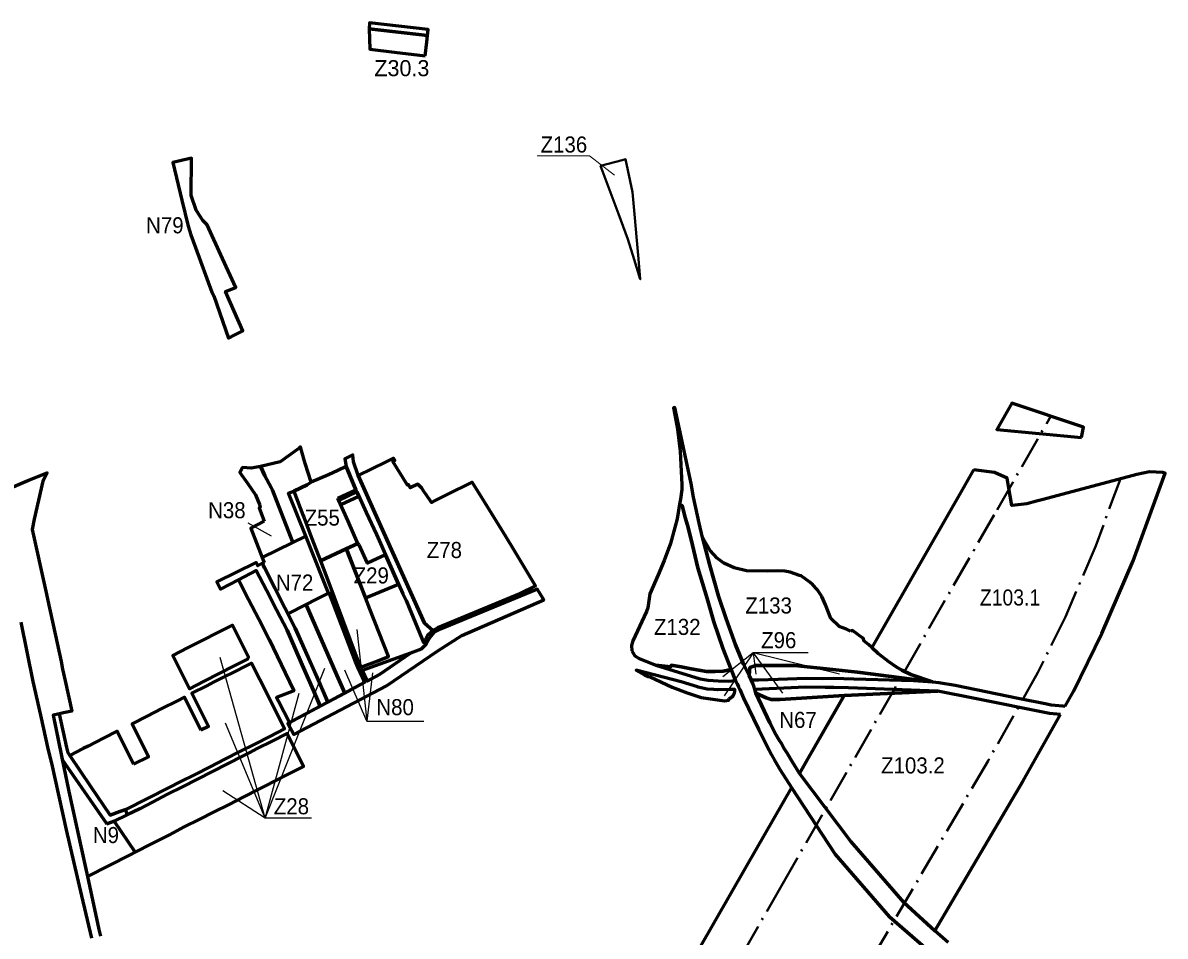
# Model space of a CAD drawing. Extents: x -650277 to -643425, y -1073980 to -1066720.
# Drawn here: x -648765 to -647061, y -1068122 to -1066758 of the extents above; entities that cross this region are included whole.
import ezdxf

# ---------------------------------------------------------------- set-up
doc = ezdxf.new("R2010")
doc.units = 0
doc.header["$LTSCALE"] = 9.6
doc.linetypes.add('DOT_DASHED', pattern=[7.7, 5, -1.2, 0.3, -1.2])
for name, color, linetype, lineweight in [('1', 7, 'Continuous', 60), ('15', 7, 'Continuous', 60), ('2', 7, 'Continuous', 40), ('3', 7, 'Continuous', 60), ('42', 7, 'Continuous', 60), ('45', 7, 'Continuous', 60), ('48', 7, 'Continuous', 60), ('59', 7, 'Continuous', 25), ('60', 7, 'Continuous', 60), ('61', 7, 'Continuous', 60), ('62', 7, 'DOT_DASHED', 40), ('63', 7, 'Continuous', 25), ('7', 7, 'Continuous', 60), ('9', 7, 'Continuous', 60)]:
    doc.layers.add(name, color=color, linetype=linetype, lineweight=lineweight)

msp = doc.modelspace()

# ---------------------------------------------------------------- linework, layer by layer
at = {"layer": '1'}
msp.add_line((-648609.91, -1067940.58), (-648611.61, -1067932.63), dxfattribs=at)
for points in [[(-647708.71, -1067723.99), (-647721.05, -1067691.73), (-647734.63, -1067652.57), (-647744.61, -1067617.96), (-647758.25, -1067571.79), (-647768.5, -1067529.75), (-647773.96, -1067508.48), (-647777.55, -1067496.95), (-647781.85, -1067479.19), (-647785.64, -1067477.02), (-647789.39, -1067498.84), (-647792.54, -1067511.85), (-647799.39, -1067535.48)], [(-647704.458, -1067572.034), (-647719.661, -1067564.884), (-647729.802, -1067557.462), (-647740.124, -1067546.265), (-647751.41, -1067526.58), (-647740.49, -1067568.67), (-647727.37, -1067614.33), (-647715.92, -1067648.12), (-647702.04, -1067686.86), (-647690.09, -1067716.05), (-647681.91, -1067732.74), (-647680.804, -1067720.745), (-647672, -1067718), (-647643, -1067718), (-647614, -1067718), (-647557, -1067724), (-647520.145, -1067727.879), (-647408.2, -1067742.37)], [(-648263.7, -1067537.93), (-648265.757, -1067535.555), (-648282.863, -1067543.596), (-648281.774, -1067546.369), (-648254.04, -1067616.96)], [(-648224.16, -1067552.55), (-648251.33, -1067565.28), (-648263.7, -1067537.93)], [(-647799.39, -1067535.48), (-647808.71, -1067561.03), (-647817.59, -1067582.4)], [(-648254.04, -1067616.96), (-648204.88, -1067596.54), (-648224.16, -1067552.55)], [(-647591.227, -1067593.613), (-647604.415, -1067584.047), (-647606.559, -1067583.309), (-647620.586, -1067578.478), (-647628.441, -1067576.759), (-647640.087, -1067576.306), (-647654.743, -1067576.996), (-647685.968, -1067576.68), (-647704.458, -1067572.034)], [(-647817.59, -1067582.4), (-647829.97, -1067610.62), (-647832.8, -1067631.53), (-647835.06, -1067637.01), (-647855.24, -1067681.26), (-647857.51, -1067687.74), (-647856.9, -1067695.97)], [(-647573.605, -1067614.951), (-647580.539, -1067604.432), (-647586.864, -1067597.411), (-647591.227, -1067593.613)], [(-647530.82, -1067666.65), (-647536.83, -1067663.64), (-647547.663, -1067659.519), (-647560.187, -1067647.458), (-647567.744, -1067627.24), (-647573.605, -1067614.951)], [(-647499.095, -1067691.163), (-647503.97, -1067686.73), (-647510.6, -1067680.86), (-647511.24, -1067677.53), (-647517.74, -1067672.85), (-647520.13, -1067671.13), (-647527.76, -1067665.65), (-647530.82, -1067666.65)], [(-647856.9, -1067695.97), (-647852.3, -1067703.36), (-647845.74, -1067707.59), (-647821.02, -1067717.33)], [(-647474.13, -1067711.81), (-647489.3, -1067700.07), (-647499.095, -1067691.163)], [(-648399.64, -1067763.26), (-648424.14, -1067714.34), (-648435.34, -1067720.01), (-648446.58, -1067725.71), (-648468.97, -1067736.91), (-648480.06, -1067742.47), (-648491.14, -1067748.02), (-648513.23, -1067759.38), (-648488.49, -1067808.76), (-648499.7, -1067814.37)], [(-647453.87, -1067724.97), (-647462.45, -1067719.84), (-647474.13, -1067711.81)], [(-647821.02, -1067717.33), (-647798.5, -1067719.67), (-647798.17, -1067717.58), (-647783.13, -1067719.68), (-647768.53, -1067722.82), (-647745.41, -1067726.6), (-647732.71, -1067727.02), (-647720.45, -1067726.49), (-647708.71, -1067723.99)], [(-647408.2, -1067742.37), (-647440.81, -1067731.38), (-647453.87, -1067724.97)], [(-648611.61, -1067932.63), (-648547.09, -1067899.87), (-648530.81, -1067891.61), (-648508.22, -1067880.38), (-648486.09, -1067868.98), (-648463.91, -1067857.74), (-648441.47, -1067846.37), (-648419.44, -1067835.3), (-648397.04, -1067823.85), (-648374.84, -1067812.43), (-648399.64, -1067763.26)], [(-648499.7, -1067814.37), (-648524.44, -1067765.11), (-648535.61, -1067770.85), (-648557.84, -1067782.26), (-648580.14, -1067793.61), (-648602.3, -1067804.83), (-648577.78, -1067854.07), (-648600.14, -1067865.29)], [(-648600.14, -1067865.29), (-648624.76, -1067816.11), (-648645.11, -1067826.48), (-648668.085, -1067838.186), (-648675.26, -1067841.84), (-648695.27, -1067852.04), (-648664.41, -1067897.91)], [(-648572.5, -1067983.59), (-648546.76, -1067970.44), (-648524.72, -1067958.93), (-648502.59, -1067948), (-648480.12, -1067936.55), (-648457.87, -1067925.4), (-648435.55, -1067913.84), (-648413.41, -1067902.53), (-648402.29, -1067897.02), (-648391.08, -1067891.24), (-648368.78, -1067879.75), (-648346.57, -1067868.56), (-648371.27, -1067819.47), (-648393.35, -1067830.81), (-648415.69, -1067841.98), (-648426.65, -1067847.64), (-648437.89, -1067853.4), (-648460.33, -1067864.88), (-648482.5, -1067876.22), (-648504.92, -1067887.52), (-648527.33, -1067898.74), (-648549.44, -1067910.07), (-648571.88, -1067921.71), (-648591.04, -1067931.62), (-648609.91, -1067940.58)], [(-648664.41, -1067897.91), (-648635.249, -1067941.252), (-648620.658, -1067935.93), (-648611.61, -1067932.63)], [(-648609.91, -1067940.58), (-648629.22, -1067950.214), (-648597.93, -1067996.72), (-648572.5, -1067983.59)]]:
    msp.add_lwpolyline(points, dxfattribs=at)
for points in [[(-648397.98, -1067678.79), (-648373.99, -1067728.95), (-648361.08, -1067755.88), (-648387.04, -1067765.67), (-648384.25, -1067771.07), (-648367.811, -1067802.994), (-648321.623, -1067778.399), (-648326, -1067769), (-648337.32, -1067742.59), (-648348.55, -1067716.71), (-648359.6, -1067691.58), (-648371.34, -1067665.08), (-648386.91, -1067634.83), (-648402.02, -1067605.49), (-648417.12, -1067576.17), (-648443.83, -1067589.92), (-648428.7, -1067619.24), (-648413.57, -1067648.57)], [(-648342.697, -1067626.806), (-648369.949, -1067640.851), (-648359.213, -1067661.956), (-648310.511, -1067772.476), (-648285.254, -1067759.008), (-648296.891, -1067732.172), (-648342.023, -1067628.096)], [(-648519.63, -1067691.58), (-648541.86, -1067702.86), (-648516.73, -1067752.57), (-648494.84, -1067741.06), (-648472.5, -1067729.76), (-648450.23, -1067718.32), (-648430.17, -1067708.33), (-648428.67, -1067705.52), (-648452.72, -1067657.62)]]:
    msp.add_lwpolyline(points, close=True, dxfattribs=at)
at = {"layer": '1', "lineweight": 25}
msp.add_lwpolyline([(-648335, -1067946), (-648404, -1067946), (-648353, -1067759)], dxfattribs=at)
at = {"layer": '15'}
msp.add_line((-648264.34, -1067464.83), (-648267.21, -1067458.61), dxfattribs=at)
msp.add_line((-648264.34, -1067464.83), (-648267.21, -1067458.61), dxfattribs=at)
msp.add_line((-648264.34, -1067464.83), (-648267.21, -1067458.61), dxfattribs=at)
for points in [[(-648161.58, -1066777.41), (-648160.51, -1066768.4), (-648248.43, -1066758.34), (-648248.77, -1066767.43)], [(-648362.585, -1067534.204), (-648343.41, -1067524.81), (-648369.01, -1067460.52), (-648361, -1067457.36), (-648341.15, -1067448.14), (-648335.38, -1067444.07), (-648344.41, -1067416.04), (-648349.67, -1067396.88), (-648351.06, -1067391.62), (-648352.16, -1067392.42), (-648353.35, -1067393.29), (-648381.48, -1067413.68), (-648410.92, -1067420.63), (-648409.61, -1067423.44), (-648404.29, -1067434.9), (-648394.92, -1067452.23), (-648393.17, -1067455.88)], [(-648237.81, -1067522.42), (-648204.88, -1067596.54), (-648198.39, -1067610.97), (-648193.8, -1067621), (-648189.03, -1067631.71), (-648167.48, -1067683.45), (-648164.79, -1067678.96), (-648163.11, -1067676.17), (-648160.68, -1067671.55), (-648153.98, -1067665.43), (-648166.173, -1067654.853), (-648240.51, -1067489.9), (-648265.197, -1067434.03), (-648265.197, -1067434.03), (-648272.022, -1067413.59), (-648273.008, -1067403.338), (-648279.24, -1067406.38), (-648285.08, -1067409.24), (-648283.21, -1067420.88), (-648268.67, -1067455.43), (-648267.21, -1067458.61), (-648264.34, -1067464.83), (-648253.1, -1067489.23)], [(-648359.6, -1067691.58), (-648348.55, -1067716.71), (-648337.32, -1067742.59), (-648326, -1067769), (-648321.623, -1067778.399), (-648310.511, -1067772.476), (-648323.178, -1067741.953), (-648359.213, -1067661.956), (-648405.054, -1067571.837), (-648408.002, -1067565.219), (-648414.73, -1067568.8), (-648417.19, -1067564.02), (-648475.78, -1067593.11), (-648473.34, -1067598.06), (-648470.57, -1067603.69), (-648470.47, -1067603.64), (-648443.83, -1067589.92), (-648417.12, -1067576.17), (-648402.02, -1067605.49), (-648386.91, -1067634.83), (-648371.34, -1067665.08)], [(-647988.235, -1067619.912), (-647995.04, -1067608.56), (-647997.68, -1067604.11), (-648144.83, -1067664.48), (-648151.6, -1067668.12), (-648157.2, -1067674.32), (-648161, -1067680.96), (-648162.69, -1067684), (-648164.09, -1067686.51), (-648171.21, -1067693.37), (-648187.139, -1067699.179), (-648233.264, -1067731.288), (-648251.711, -1067741.124), (-648258.96, -1067725.37), (-648262.632, -1067726.711), (-648255.016, -1067742.886), (-648319.983, -1067777.526), (-648370.113, -1067804.22), (-648360.993, -1067821.027), (-648222.872, -1067748.412), (-648146.127, -1067695.8), (-648110.36, -1067673.133), (-647988.052, -1067619.624)]]:
    msp.add_lwpolyline(points, close=True, dxfattribs=at)
for points in [[(-648793.71, -1067456.88), (-648757.97, -1067441.51), (-648728.95, -1067430.33), (-648735.59, -1067442.88), (-648748.53, -1067499.3), (-648751.29, -1067514.57), (-648731.06, -1067607.06), (-648725.8, -1067632.36), (-648720.1, -1067657.12), (-648708.26, -1067712.07), (-648706.08, -1067723.56), (-648702.33, -1067740.84), (-648692.53, -1067785.79), (-648704.614, -1067788.491), (-648710.961, -1067789.906), (-648720.34, -1067792), (-648696.93, -1067905.76), (-648672.31, -1068017.25), (-648668.92, -1068032.96), (-648651.89, -1068111.95), (-648649.74, -1068121.95)], [(-648267.21, -1067458.61), (-648294.04, -1067471.35), (-648291.172, -1067477.571), (-648264.34, -1067464.83)], [(-648267.21, -1067458.61), (-648294.04, -1067471.35), (-648291.172, -1067477.571), (-648264.34, -1067464.83)], [(-648267.21, -1067458.61), (-648294.04, -1067471.35), (-648291.172, -1067477.571), (-648264.34, -1067464.83)], [(-648662.71, -1068124.76), (-648677.61, -1068061.74), (-648700.16, -1067963.42), (-648722.09, -1067863.84), (-648727.05, -1067844.33), (-648738.7, -1067792.04), (-648749.97, -1067741.49), (-648767.84, -1067652.98)], [(-648710.961, -1067789.906), (-648720.34, -1067792), (-648706.687, -1067858.345), (-648640, -1067954)], [(-648695.27, -1067852.04), (-648697.7, -1067848.43), (-648699.621, -1067840.06), (-648699.593, -1067840.046), (-648710.96, -1067789.91)], [(-648611.61, -1067932.63), (-648620.658, -1067935.93), (-648635.249, -1067941.252), (-648664.41, -1067897.91), (-648695.27, -1067852.04)], [(-648640, -1067954), (-648629.22, -1067950.214), (-648609.91, -1067940.58), (-648611.61, -1067932.63)]]:
    msp.add_lwpolyline(points, dxfattribs=at)
at = {"layer": '2'}
msp.add_lwpolyline([(-647876.57, -1067043.5), (-647863.04, -1067081.36), (-647853.65, -1067111.91), (-647844.3, -1067141.25), (-647847.09, -1067110.58), (-647850.07, -1067077.71), (-647852.63, -1067049.52), (-647856.11, -1067011.21), (-647866.14, -1066961.98), (-647871.52, -1066963.43), (-647903.5, -1066972.05), (-647903.5, -1066972.05)], close=True, dxfattribs=at)
at = {"layer": '3'}
msp.add_lwpolyline([(-648165.33, -1066807.74), (-648162.8, -1066786.8), (-648161.58, -1066777.41), (-648248.77, -1066767.43), (-648247.78, -1066797.53), (-648211.58, -1066802.18)], close=True, dxfattribs=at)
at = {"layer": '42'}
msp.add_lwpolyline([(-647606.818, -1067879.061), (-647540.208, -1067762.876), (-647635.758, -1067768.38), (-647649.22, -1067768.38), (-647656.469, -1067766.309), (-647672.05, -1067758.98), (-647650.8, -1067803.28), (-647642.29, -1067820.76), (-647637.21, -1067829.29), (-647633.69, -1067834.31), (-647630.3, -1067841.02), (-647625.37, -1067848.86), (-647617.25, -1067861.95)], close=True, dxfattribs=at)
at = {"layer": '45'}
msp.add_lwpolyline([(-648405.41, -1067563.84), (-648408.002, -1067565.219), (-648369.949, -1067640.851), (-648342.697, -1067626.806), (-648328.54, -1067619.51), (-648309.522, -1067609.713), (-648317.43, -1067590), (-648343.41, -1067524.81), (-648408.26, -1067556.58)], close=True, dxfattribs=at)
at = {"layer": '48'}
for points in [[(-648528.01, -1067023.13), (-648518.72, -1067061.99), (-648514.86, -1067074.83), (-648507.88, -1067093.9), (-648483.31, -1067160.63), (-648480.57, -1067166.13), (-648458.73, -1067229.1), (-648449.03, -1067224.14), (-648437.02, -1067217.99), (-648462.97, -1067159.24), (-648447.66, -1067153.25), (-648467.56, -1067110.02), (-648490.23, -1067060.06), (-648496.87, -1067053.5), (-648506.78, -1067037.81), (-648514.38, -1067016.2), (-648513.842, -1066960.243), (-648541.52, -1066966.657)], [(-648405.27, -1067502.27), (-648425.5, -1067512.73), (-648408.26, -1067556.58), (-648362.585, -1067534.205), (-648393.17, -1067455.88), (-648394.92, -1067452.23), (-648404.29, -1067434.9), (-648410.92, -1067420.63), (-648425, -1067423.05), (-648437.75, -1067421.99), (-648441.48, -1067429.63), (-648430.4, -1067445.51), (-648418.3, -1067462.86), (-648412.46, -1067477.42), (-648411.25, -1067481.73), (-648412.89, -1067482.55)], [(-648342.023, -1067628.096), (-648296.891, -1067732.172), (-648285.254, -1067759.008), (-648255.016, -1067742.886), (-648265.614, -1067720.378), (-648269.27, -1067712.6), (-648308.43, -1067609.15), (-648328.54, -1067619.51), (-648342.697, -1067626.806)], [(-648258.96, -1067725.37), (-648251.711, -1067741.124), (-648233.264, -1067731.288), (-648187.139, -1067699.179)]]:
    msp.add_lwpolyline(points, close=True, dxfattribs=at)
for points in [[(-648295.409, -1067468.129), (-648268.67, -1067455.43), (-648283.21, -1067420.88), (-648295.66, -1067426.76), (-648309.57, -1067433.34), (-648335.38, -1067444.07), (-648341.15, -1067448.14), (-648361, -1067457.36), (-648347.51, -1067492.87), (-648346.27, -1067496.14)], [(-648346.27, -1067496.14), (-648334.09, -1067528.2), (-648321.36, -1067561.69), (-648282.863, -1067543.596), (-648265.757, -1067535.555), (-648279.86, -1067502.11), (-648294.04, -1067471.35), (-648295.409, -1067468.129)], [(-648265.08, -1067712.06), (-648261.25, -1067720.39), (-648235.78, -1067710.79), (-648219.86, -1067704.42), (-648247.53, -1067633.53), (-648254.04, -1067616.96), (-648282.863, -1067543.596), (-648321.36, -1067561.69)], [(-648321.361, -1067561.69), (-648311.95, -1067586.45), (-648265.08, -1067712.06)]]:
    msp.add_lwpolyline(points, dxfattribs=at)
at = {"layer": '59', "lineweight": 13}
msp.add_lwpolyline([(-647998, -1066957), (-647920, -1066957), (-647883, -1066986)], dxfattribs=at)
at = {"layer": '60'}
for points in [[(-647606.818, -1067879.061), (-647617.25, -1067861.95), (-647625.37, -1067848.86), (-647630.3, -1067841.02), (-647633.69, -1067834.31), (-647637.21, -1067829.29), (-647642.29, -1067820.76), (-647650.8, -1067803.28), (-647672.05, -1067758.98), (-647673.47, -1067753.48), (-647673.47, -1067753.48), (-647674.67, -1067748.73), (-647676.47, -1067744.5), (-647678.66, -1067739.38), (-647681.91, -1067732.74), (-647690.09, -1067716.05), (-647702.04, -1067686.86), (-647715.92, -1067648.12), (-647727.37, -1067614.33), (-647740.49, -1067568.67), (-647751.41, -1067526.58), (-647756.55, -1067505.32), (-647759.16, -1067494.01), (-647764.89, -1067466.64), (-647768.5, -1067446.04), (-647778.78, -1067397.1), (-647792.52, -1067332.74), (-647794.54, -1067333.14), (-647788.77, -1067365.03), (-647784.55, -1067398.01), (-647782.39, -1067448.34), (-647782.5, -1067455.11), (-647784.36, -1067469.6), (-647785.64, -1067477.02), (-647781.85, -1067479.19), (-647777.55, -1067496.95), (-647773.96, -1067508.48), (-647768.5, -1067529.75), (-647758.25, -1067571.79), (-647744.61, -1067617.96), (-647734.63, -1067652.57), (-647721.05, -1067691.73), (-647708.71, -1067723.99), (-647702.21, -1067740.43), (-647699.89, -1067745.24), (-647697.85, -1067749.46), (-647695.71, -1067753.9), (-647690.19, -1067766.37), (-647668.13, -1067812.76), (-647651.94, -1067844.36), (-647648.33, -1067851.17), (-647643.83, -1067859.13), (-647635.77, -1067873.43), (-647618.773, -1067899.914)], [(-647783.54, -1067742.11), (-647850.45, -1067724.77), (-647838.18, -1067731.62), (-647832.56, -1067734.22), (-647829.49, -1067734.58), (-647796.87, -1067750.25), (-647774.54, -1067758.68), (-647753.53, -1067765.58), (-647718.54, -1067770.6), (-647712.01, -1067769.63), (-647712.26, -1067767.28)], [(-647712.26, -1067767.28), (-647711.773, -1067767.135), (-647711.286, -1067766.968), (-647710.799, -1067766.777), (-647710.315, -1067766.562), (-647709.834, -1067766.324), (-647709.359, -1067766.062), (-647708.892, -1067765.776), (-647708.433, -1067765.466), (-647707.985, -1067765.133), (-647707.55, -1067764.777), (-647707.128, -1067764.398), (-647706.723, -1067763.999), (-647706.335, -1067763.579), (-647705.966, -1067763.14), (-647705.617, -1067762.683), (-647705.29, -1067762.21), (-647704.985, -1067761.721), (-647704.704, -1067761.22), (-647704.447, -1067760.707), (-647704.216, -1067760.184), (-647704.01, -1067759.653), (-647703.83, -1067759.117), (-647703.675, -1067758.576), (-647703.547, -1067758.033), (-647703.445, -1067757.489), (-647703.368, -1067756.946), (-647703.315, -1067756.406), (-647703.287, -1067755.87), (-647703.282, -1067755.341), (-647703.3, -1067754.818), (-647703.34, -1067754.304), (-647703.4, -1067753.8), (-647711.09, -1067753.71), (-647728.98, -1067754.07), (-647734.69, -1067753.66), (-647744.74, -1067752.93), (-647757.74, -1067749.96), (-647759.13, -1067749.54), (-647783.54, -1067742.11)], [(-647405.026, -1068113.904), (-647451.024, -1068071.886), (-647530.038, -1067980.839), (-647606.818, -1067879.061)], [(-647618.773, -1067899.914), (-647553.628, -1067999.427), (-647472.338, -1068093.096), (-647419.713, -1068138.871)], [(-647385.13, -1068131.51), (-647405.026, -1068113.904)]]:
    msp.add_lwpolyline(points, dxfattribs=at)
for points in [[(-647754.88, -1067737.59), (-647743.12, -1067739.93), (-647728.29, -1067740.64), (-647713.15, -1067741), (-647702.21, -1067740.43), (-647708.71, -1067723.99), (-647720.45, -1067726.49), (-647732.71, -1067727.02), (-647745.41, -1067726.6), (-647768.53, -1067722.82), (-647783.13, -1067719.68), (-647798.17, -1067717.58), (-647798.5, -1067719.67), (-647821.02, -1067717.33)], [(-647596.91, -1067736.61), (-647572.33, -1067737.03), (-647555.58, -1067736.71), (-647525.685, -1067737.542), (-647436.72, -1067740.02), (-647408.2, -1067742.37), (-647520.145, -1067727.879), (-647557, -1067724), (-647614, -1067718), (-647643, -1067718), (-647672, -1067718), (-647680.804, -1067720.745), (-647681.91, -1067732.74), (-647678.66, -1067739.38), (-647678.66, -1067739.38), (-647667.76, -1067739.01), (-647638.75, -1067738.03)], [(-647540.208, -1067762.876), (-647400.63, -1067756.19), (-647533.597, -1067751.344), (-647555.67, -1067750.91), (-647568.36, -1067750.7), (-647597.83, -1067750.21), (-647673.47, -1067753.48), (-647672.05, -1067758.98), (-647672.05, -1067758.98), (-647656.469, -1067766.309), (-647649.22, -1067768.38), (-647635.758, -1067768.38)]]:
    msp.add_lwpolyline(points, close=True, dxfattribs=at)
at = {"layer": '61'}
msp.add_lwpolyline([(-647185.93, -1067377.38), (-647184.97, -1067372.22), (-647183.09, -1067362.16), (-647289.924, -1067326.309), (-647312.383, -1067365.484)], close=True, dxfattribs=at)
for points in [[(-647346.944, -1067425.768), (-647364.024, -1067455.561), (-647499.095, -1067691.163), (-647489.3, -1067700.07)], [(-647243.39, -1067469.81), (-647252.99, -1067472.35), (-647267.49, -1067476.23), (-647290.23, -1067478.89), (-647292.51, -1067464.56), (-647294.31, -1067453.26), (-647296.75, -1067437.91), (-647315.89, -1067429.71), (-647346.944, -1067425.768)], [(-647061.252, -1067430.908), (-647061.252, -1067430.908), (-647063.45, -1067430.19), (-647064.87, -1067429.73), (-647084.77, -1067428.64), (-647103.55, -1067432.54), (-647243.39, -1067469.81)], [(-647210.537, -1067778.594), (-647198.088, -1067756.5), (-647155.592, -1067670.17), (-647108.971, -1067561.55), (-647061.252, -1067430.908)], [(-647489.3, -1067700.07), (-647474.13, -1067711.81), (-647462.45, -1067719.84), (-647453.87, -1067724.97), (-647440.81, -1067731.38), (-647408.2, -1067742.37), (-647398.74, -1067743.15), (-647374.55, -1067747.34)], [(-647374.55, -1067747.34), (-647280.78, -1067766.44), (-647237.91, -1067775.18), (-647231.17, -1067776.55), (-647213.92, -1067778.26), (-647210.537, -1067778.594)], [(-647400.63, -1067756.19), (-647540.208, -1067762.876), (-647593.267, -1067855.425), (-647606.818, -1067879.061)], [(-647217.611, -1067791.149), (-647233.83, -1067789.69), (-647345.11, -1067767.28), (-647400.63, -1067756.19)], [(-647405.026, -1068113.904), (-647273.297, -1067889.981), (-647217.611, -1067791.149)], [(-647606.818, -1067879.061), (-647530.038, -1067980.839), (-647451.024, -1068071.886), (-647405.026, -1068113.904)], [(-647464.94, -1068215.752), (-647461.188, -1068209.373), (-647419.713, -1068138.871), (-647472.338, -1068093.096), (-647553.628, -1067999.427), (-647618.773, -1067899.914), (-647685.819, -1068016.861)], [(-647685.819, -1068016.861), (-647781.346, -1068183.485), (-647791.055, -1068200.507)]]:
    msp.add_lwpolyline(points, dxfattribs=at)
at = {"layer": '62'}
for points in [[(-647729.261, -1068213.27), (-647633.767, -1068046.703), (-647560.654, -1067919.174), (-647311.972, -1067485.403), (-647231.921, -1067345.773)], [(-647128.118, -1067439.088), (-647164.761, -1067539.408), (-647210.113, -1067645.071), (-647251.182, -1067728.502), (-647325.296, -1067860.04), (-647512.903, -1068178.95), (-647726.877, -1068542.68), (-647850.594, -1068756.441), (-647875.691, -1068807.609), (-647903.473, -1068876.174), (-647924.037, -1068940.973), (-647945.559, -1069039.601), (-647956.348, -1069145.994), (-647956.677, -1069214.977), (-647954.925, -1069248.93), (-647950.785, -1069292.731), (-647945.699, -1069329.377), (-647937.748, -1069374.683)]]:
    msp.add_lwpolyline(points, dxfattribs=at)
at = {"layer": '63'}
for p, q in [((-648430, -1067505), (-648395, -1067524)), ((-648404, -1067946), (-648471, -1067706)), ((-647676, -1067699), (-647672, -1067731)), ((-647676, -1067699), (-647632, -1067759)), ((-648404, -1067946), (-648315, -1067722)), ((-648404, -1067946), (-648463, -1067804))]:
    msp.add_line(p, q, dxfattribs=at)
for points in [[(-648267, -1067664), (-648252, -1067801), (-648285, -1067725)], [(-647594, -1067699), (-647676, -1067699), (-647721, -1067735)], [(-647547, -1067731), (-647676, -1067699), (-647719, -1067763)], [(-648244, -1067729), (-648252, -1067801), (-648285, -1067725)], [(-648244, -1067729), (-648252, -1067801), (-648167, -1067801)], [(-648335, -1067946), (-648404, -1067946), (-648467, -1067905)]]:
    msp.add_lwpolyline(points, dxfattribs=at)
at = {"layer": '7'}
msp.add_lwpolyline([(-648640, -1067954), (-648706.687, -1067858.345), (-648696.93, -1067905.76), (-648668.92, -1068032.96), (-648605.323, -1068000.463), (-648597.93, -1067996.72), (-648629.22, -1067950.214)], close=True, dxfattribs=at)
at = {"layer": '9'}
msp.add_lwpolyline([(-648153.98, -1067665.43), (-648149.933, -1067663.646), (-648146.21, -1067661.3), (-648023.96, -1067610.13), (-648000.63, -1067599.14), (-648031.77, -1067546.6), (-648045.04, -1067525.15), (-648076.32, -1067474.6), (-648081.31, -1067466.54), (-648095.28, -1067444.06), (-648133.56, -1067463.2), (-648150.46, -1067471.66), (-648155.85, -1067474.35), (-648164.24, -1067462.15), (-648166.97, -1067458.18), (-648170.38, -1067453.23), (-648175.94, -1067446.89), (-648187.44, -1067452.8), (-648190.23, -1067447.83), (-648191.46, -1067448.59), (-648213.34, -1067413.46), (-648210.48, -1067411.68), (-648211.08, -1067410.6), (-648212.32, -1067408.39), (-648224.19, -1067414.14), (-648265.197, -1067434.03), (-648240.51, -1067489.9), (-648240.51, -1067489.9), (-648166.173, -1067654.853)], close=True, dxfattribs=at)

# ---------------------------------------------------------------- texts
at = {"layer": '59', "width": 0.95}
for s, p in [('Z136', (-647993, -1066952)), ('N38', (-648489, -1067498)), ('Z29', (-648271.915, -1067595.341)), ('N80', (-648238, -1067792))]:
    msp.add_text(s, height=24, dxfattribs=at).set_placement(p)
at = {"layer": '63'}
msp.add_text('Z30.3', height=24, dxfattribs=at).set_placement((-648241, -1066838))
for s, width, p in [('N79', 0.95, (-648581.544, -1067072.648)), ('N38', 0.95, (-648489, -1067498)), ('Z55', 0.95, (-648345, -1067509)), ('Z78', 0.95, (-648162.836, -1067557.421)), ('N72', 0.95, (-648388, -1067606)), ('Z103.1', 0.9, (-647337.666, -1067628.26)), ('Z133', 0.95, (-647687.579, -1067640.215)), ('Z132', 0.95, (-647823.879, -1067672.215)), ('Z96', 0.95, (-647664, -1067692)), ('N80', 0.95, (-648238, -1067792)), ('N67', 0.95, (-647636.885, -1067811.038)), ('Z103.2', 0.95, (-647485, -1067879)), ('Z28', 0.95, (-648391, -1067940)), ('N9', 0.95, (-648661, -1067983))]:
    msp.add_text(s, height=24, dxfattribs=dict(at, width=width)).set_placement(p)

doc.saveas('drawing.dxf')
